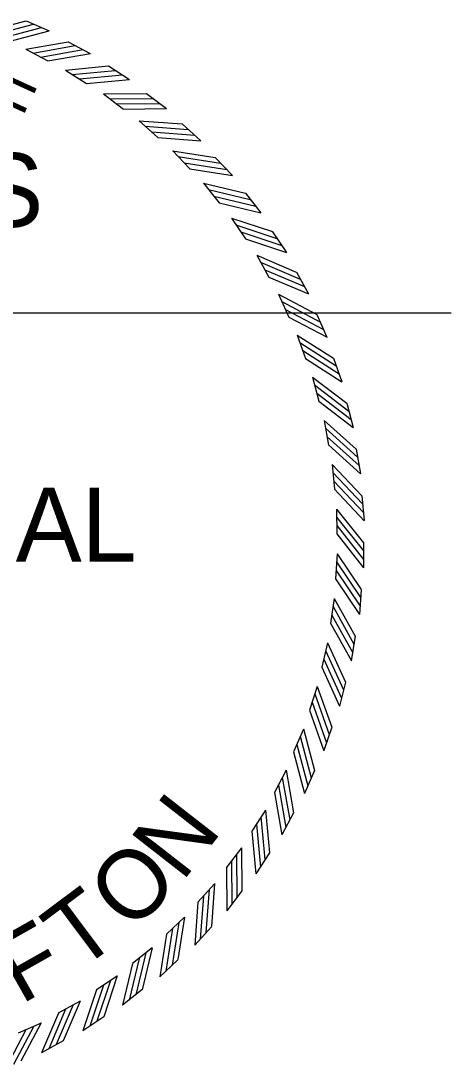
# Model space of a CAD drawing. Extents: x -712 to 3943, y 73 to 2823.
# Drawn here: x 3144.5 to 3223.6, y 210.4 to 403.1 of the extents above; entities that cross this region are included whole.
import ezdxf

# ---------------------------------------------------------------- set-up
doc = ezdxf.new("R2010")
doc.units = 0
doc.layers.add('SHET_Border-Lines', color=7, linetype='Continuous')
doc.layers.add('STAMP_TNC', color=7, linetype='Continuous')

msp = doc.modelspace()

# ---------------------------------------------------------------- linework, layer by layer
at = {"layer": 'SHET_Border-Lines'}
msp.add_lwpolyline([(2989.35, 349.36), (3223.63, 349.36)], dxfattribs=at)
msp.add_lwpolyline([(2989.35, 349.36), (3223.63, 349.36)], dxfattribs=at)
at = {"layer": 'STAMP_TNC'}
for p, q in [((3145.47, 403.1), (3149.69, 401.3)), ((3145.47, 403.1), (3149.69, 401.3)), ((3153.21, 399.26), (3157.26, 397.12)), ((3153.21, 399.26), (3157.26, 397.12)), ((3145.41, 397.88), (3149.47, 395.73)), ((3145.41, 397.88), (3149.47, 395.73)), ((3152.72, 394.07), (3156.58, 391.59)), ((3152.72, 394.07), (3156.58, 391.59)), ((3160.61, 394.81), (3164.47, 392.33)), ((3160.61, 394.81), (3164.47, 392.33)), ((3159.69, 389.67), (3163.34, 386.88)), ((3159.69, 389.67), (3163.34, 386.88)), ((3167.61, 389.75), (3171.26, 386.97)), ((3167.61, 389.75), (3171.26, 386.97)), ((3166.27, 384.71), (3169.68, 381.63)), ((3166.27, 384.71), (3169.68, 381.63)), ((3174.18, 384.14), (3177.58, 381.06)), ((3174.18, 384.14), (3177.58, 381.06)), ((3172.42, 379.22), (3175.56, 375.87)), ((3172.42, 379.22), (3175.56, 375.87)), ((3180.25, 378), (3183.39, 374.65)), ((3180.25, 378), (3183.39, 374.65)), ((3178.1, 373.25), (3180.95, 369.65)), ((3178.1, 373.25), (3180.95, 369.65)), ((3185.8, 371.38), (3188.65, 367.79)), ((3185.8, 371.38), (3188.65, 367.79)), ((3183.26, 366.82), (3185.81, 363)), ((3183.26, 366.82), (3185.81, 363)), ((3190.78, 364.32), (3193.33, 360.51)), ((3190.78, 364.32), (3193.33, 360.51)), ((3187.87, 359.99), (3190.1, 355.97)), ((3187.87, 359.99), (3190.1, 355.97)), ((3195.17, 356.88), (3197.39, 352.87)), ((3195.17, 356.88), (3197.39, 352.87)), ((3191.91, 352.8), (3193.79, 348.62)), ((3191.91, 352.8), (3193.79, 348.62)), ((3198.92, 349.1), (3200.8, 344.92)), ((3198.92, 349.1), (3200.8, 344.92)), ((3195.34, 345.31), (3196.87, 340.98)), ((3195.34, 345.31), (3196.87, 340.98)), ((3202.02, 341.04), (3203.55, 336.72)), ((3202.02, 341.04), (3203.55, 336.72)), ((3198.14, 337.56), (3199.3, 333.11)), ((3198.14, 337.56), (3199.3, 333.11)), ((3204.44, 332.75), (3205.61, 328.32)), ((3204.44, 332.75), (3205.61, 328.32)), ((3200.28, 329.6), (3201.08, 325.07)), ((3200.28, 329.6), (3201.08, 325.07)), ((3206.17, 324.29), (3206.97, 319.77)), ((3206.17, 324.29), (3206.97, 319.77)), ((3201.77, 321.49), (3202.19, 316.92)), ((3201.77, 321.49), (3202.19, 316.92)), ((3207.2, 315.71), (3207.62, 311.15)), ((3207.2, 315.71), (3207.62, 311.15)), ((3202.58, 313.29), (3202.62, 308.69)), ((3202.58, 313.29), (3202.62, 308.69)), ((3207.51, 307.08), (3207.55, 302.5)), ((3207.51, 307.08), (3207.55, 302.5)), ((3202.7, 305.05), (3202.37, 300.47)), ((3202.7, 305.05), (3202.37, 300.47)), ((3202.15, 296.82), (3201.44, 292.28)), ((3202.15, 296.82), (3201.44, 292.28)), ((3207.11, 298.45), (3206.77, 293.88)), ((3207.11, 298.45), (3206.77, 293.88)), ((3206, 289.89), (3205.28, 285.36)), ((3206, 289.89), (3205.28, 285.36)), ((3200.92, 288.67), (3199.84, 284.21)), ((3200.92, 288.67), (3199.84, 284.21)), ((3204.18, 281.44), (3203.1, 276.99)), ((3204.18, 281.44), (3203.1, 276.99)), ((3199.02, 280.65), (3197.57, 276.29)), ((3199.02, 280.65), (3197.57, 276.29)), ((3196.47, 272.81), (3194.66, 268.59)), ((3196.47, 272.81), (3194.66, 268.59)), ((3201.67, 273.18), (3200.23, 268.83)), ((3201.67, 273.18), (3200.23, 268.83)), ((3193.28, 265.21), (3191.13, 261.15)), ((3193.28, 265.21), (3191.13, 261.15)), ((3198.49, 265.15), (3196.69, 260.93)), ((3198.49, 265.15), (3196.69, 260.93)), ((3189.47, 257.9), (3186.99, 254.04)), ((3189.47, 257.9), (3186.99, 254.04)), ((3194.66, 257.41), (3192.52, 253.36)), ((3194.66, 257.41), (3192.52, 253.36)), ((3185.07, 250.93), (3182.28, 247.28)), ((3185.07, 250.93), (3182.28, 247.28)), ((3190.2, 250.01), (3187.73, 246.15)), ((3190.2, 250.01), (3187.73, 246.15)), ((3180.11, 244.35), (3177.03, 240.94)), ((3180.11, 244.35), (3177.03, 240.94)), ((3185.15, 243.01), (3182.37, 239.36)), ((3185.15, 243.01), (3182.37, 239.36)), ((3174.62, 238.2), (3171.27, 235.06)), ((3174.62, 238.2), (3171.27, 235.06)), ((3179.53, 236.44), (3176.46, 233.04)), ((3179.53, 236.44), (3176.46, 233.04)), ((3168.64, 232.52), (3165.04, 229.67)), ((3168.64, 232.52), (3165.04, 229.67)), ((3173.39, 230.37), (3170.05, 227.23)), ((3173.39, 230.37), (3170.05, 227.23)), ((3162.22, 227.36), (3158.4, 224.81)), ((3162.22, 227.36), (3158.4, 224.81)), ((3166.77, 224.82), (3163.18, 221.97)), ((3166.77, 224.82), (3163.18, 221.97)), ((3155.39, 222.75), (3151.37, 220.52)), ((3155.39, 222.75), (3151.37, 220.52)), ((3159.72, 219.84), (3155.91, 217.29)), ((3159.72, 219.84), (3155.91, 217.29)), ((3148.2, 218.71), (3144.01, 216.83)), ((3148.2, 218.71), (3144.01, 216.83)), ((3152.28, 215.45), (3148.27, 213.24)), ((3152.28, 215.45), (3148.27, 213.24))]:
    msp.add_line(p, q, dxfattribs=at)
for points in [[(3137.8, 401.07), (3145.47, 403.1)], [(3137.8, 401.07), (3145.47, 403.1)], [(3139.15, 400.48), (3146.82, 402.5)], [(3139.15, 400.48), (3146.82, 402.5)], [(3140.63, 399.89), (3148.29, 401.91)], [(3140.63, 399.89), (3148.29, 401.91)], [(3142.03, 399.27), (3149.69, 401.3)], [(3142.03, 399.27), (3149.69, 401.3)], [(3145.4, 397.88), (3153.21, 399.26)], [(3145.4, 397.88), (3153.21, 399.26)], [(3146.7, 397.18), (3154.5, 398.56)], [(3146.7, 397.18), (3154.5, 398.56)], [(3148.12, 396.46), (3155.93, 397.85)], [(3148.12, 396.46), (3155.93, 397.85)], [(3149.46, 395.74), (3157.27, 397.12)], [(3149.46, 395.74), (3157.27, 397.12)], [(3152.71, 394.07), (3160.6, 394.81)], [(3152.71, 394.07), (3160.6, 394.81)], [(3153.94, 393.26), (3161.84, 394)], [(3153.94, 393.26), (3161.84, 394)], [(3155.3, 392.43), (3163.2, 393.17)], [(3155.3, 392.43), (3163.2, 393.17)], [(3156.58, 391.6), (3164.48, 392.34)], [(3156.58, 391.6), (3164.48, 392.34)], [(3159.68, 389.67), (3167.61, 389.75)], [(3159.68, 389.67), (3167.61, 389.75)], [(3160.84, 388.76), (3168.77, 388.85)], [(3160.84, 388.76), (3168.77, 388.85)], [(3162.13, 387.83), (3170.06, 387.91)], [(3162.13, 387.83), (3170.06, 387.91)], [(3163.33, 386.89), (3171.26, 386.97)], [(3163.33, 386.89), (3171.26, 386.97)], [(3166.26, 384.71), (3174.17, 384.14)], [(3166.26, 384.71), (3174.17, 384.14)], [(3167.35, 383.71), (3175.25, 383.14)], [(3167.35, 383.71), (3175.25, 383.14)], [(3168.55, 382.67), (3176.46, 382.1)], [(3168.55, 382.67), (3176.46, 382.1)], [(3169.67, 381.64), (3177.58, 381.06)], [(3169.67, 381.64), (3177.58, 381.06)], [(3172.41, 379.22), (3180.25, 378)], [(3172.41, 379.22), (3180.25, 378)], [(3173.41, 378.14), (3181.24, 376.91)], [(3173.41, 378.14), (3181.24, 376.91)], [(3174.53, 377), (3182.36, 375.78)], [(3174.53, 377), (3182.36, 375.78)], [(3175.56, 375.88), (3183.39, 374.65)], [(3175.56, 375.88), (3183.39, 374.65)], [(3178.09, 373.25), (3185.79, 371.38)], [(3178.09, 373.25), (3185.79, 371.38)], [(3179, 372.08), (3186.7, 370.22)], [(3179, 372.08), (3186.7, 370.22)], [(3180.01, 370.86), (3187.72, 368.99)], [(3180.01, 370.86), (3187.72, 368.99)], [(3180.95, 369.65), (3188.65, 367.79)], [(3180.95, 369.65), (3188.65, 367.79)], [(3183.25, 366.82), (3190.78, 364.33)], [(3183.25, 366.82), (3190.78, 364.33)], [(3184.06, 365.59), (3191.58, 363.09)], [(3184.06, 365.59), (3191.58, 363.09)], [(3184.97, 364.28), (3192.5, 361.79)], [(3184.97, 364.28), (3192.5, 361.79)], [(3185.81, 363.01), (3193.33, 360.51)], [(3185.81, 363.01), (3193.33, 360.51)], [(3187.87, 359.99), (3195.16, 356.88)], [(3187.87, 359.99), (3195.16, 356.88)], [(3188.57, 358.7), (3195.86, 355.59)], [(3188.57, 358.7), (3195.86, 355.59)], [(3189.37, 357.32), (3196.66, 354.21)], [(3189.37, 357.32), (3196.66, 354.21)], [(3190.1, 355.98), (3197.39, 352.87)], [(3190.1, 355.98), (3197.39, 352.87)], [(3191.9, 352.81), (3198.92, 349.11)], [(3191.9, 352.81), (3198.92, 349.11)], [(3192.5, 351.46), (3199.51, 347.76)], [(3192.5, 351.46), (3199.51, 347.76)], [(3193.18, 350.02), (3200.19, 346.32)], [(3193.18, 350.02), (3200.19, 346.32)], [(3193.79, 348.62), (3200.81, 344.92)], [(3193.79, 348.62), (3200.81, 344.92)], [(3195.33, 345.31), (3202.01, 341.04)], [(3195.33, 345.31), (3202.01, 341.04)], [(3195.81, 343.92), (3202.49, 339.65)], [(3195.81, 343.92), (3202.49, 339.65)], [(3196.38, 342.43), (3203.06, 338.16)], [(3196.38, 342.43), (3203.06, 338.16)], [(3196.87, 340.99), (3203.55, 336.72)], [(3196.87, 340.99), (3203.55, 336.72)], [(3198.13, 337.56), (3204.44, 332.75)], [(3198.13, 337.56), (3204.44, 332.75)], [(3198.49, 336.13), (3204.8, 331.32)], [(3198.49, 336.13), (3204.8, 331.32)], [(3198.93, 334.6), (3205.24, 329.79)], [(3198.93, 334.6), (3205.24, 329.79)], [(3199.31, 333.12), (3205.61, 328.31)], [(3199.31, 333.12), (3205.61, 328.31)], [(3200.28, 329.6), (3206.17, 324.29)], [(3200.28, 329.6), (3206.17, 324.29)], [(3200.52, 328.15), (3206.41, 322.84)], [(3200.52, 328.15), (3206.41, 322.84)], [(3200.83, 326.59), (3206.72, 321.28)], [(3200.83, 326.59), (3206.72, 321.28)], [(3201.08, 325.08), (3206.97, 319.77)], [(3201.08, 325.08), (3206.97, 319.77)], [(3201.76, 321.49), (3207.19, 315.72)], [(3201.76, 321.49), (3207.19, 315.72)], [(3201.88, 320.03), (3207.31, 314.25)], [(3201.88, 320.03), (3207.31, 314.25)], [(3202.07, 318.44), (3207.49, 312.67)], [(3202.07, 318.44), (3207.49, 312.67)], [(3202.19, 316.92), (3207.62, 311.14)], [(3202.19, 316.92), (3207.62, 311.14)], [(3202.57, 313.29), (3207.5, 307.09)], [(3202.57, 313.29), (3207.5, 307.09)], [(3202.57, 311.82), (3207.5, 305.61)], [(3202.57, 311.82), (3207.5, 305.61)], [(3202.62, 310.23), (3207.55, 304.02)], [(3202.62, 310.23), (3207.55, 304.02)], [(3202.62, 308.7), (3207.55, 302.49)], [(3202.62, 308.7), (3207.55, 302.49)], [(3202.7, 305.05), (3207.1, 298.46)], [(3202.7, 305.05), (3207.1, 298.46)], [(3202.58, 303.58), (3206.98, 296.99)], [(3202.58, 303.58), (3206.98, 296.99)], [(3202.5, 301.99), (3206.9, 295.4)], [(3202.5, 301.99), (3206.9, 295.4)], [(3202.37, 300.47), (3206.77, 293.88)], [(3202.37, 300.47), (3206.77, 293.88)], [(3202.15, 296.83), (3205.99, 289.89)], [(3202.15, 296.83), (3205.99, 289.89)], [(3201.91, 295.37), (3205.75, 288.44)], [(3201.91, 295.37), (3205.75, 288.44)], [(3201.69, 293.79), (3205.54, 286.86)], [(3201.69, 293.79), (3205.54, 286.86)], [(3201.44, 292.29), (3205.29, 285.36)], [(3201.44, 292.29), (3205.29, 285.36)], [(3200.56, 287.25), (3203.82, 280.02)], [(3200.56, 287.25), (3203.82, 280.02)], [(3200.92, 288.68), (3204.18, 281.45)], [(3200.92, 288.68), (3204.18, 281.45)], [(3200.22, 285.69), (3203.47, 278.47)], [(3200.22, 285.69), (3203.47, 278.47)], [(3199.84, 284.21), (3203.1, 276.99)], [(3199.84, 284.21), (3203.1, 276.99)], [(3199.02, 280.66), (3201.67, 273.18)], [(3199.02, 280.66), (3201.67, 273.18)], [(3198.07, 277.74), (3200.72, 270.27)], [(3198.07, 277.74), (3200.72, 270.27)], [(3198.54, 279.26), (3201.19, 271.79)], [(3198.54, 279.26), (3201.19, 271.79)], [(3197.58, 276.3), (3200.23, 268.82)], [(3197.58, 276.3), (3200.23, 268.82)], [(3196.47, 272.82), (3198.49, 265.15)], [(3196.47, 272.82), (3198.49, 265.15)], [(3195.28, 269.99), (3197.31, 262.33)], [(3195.28, 269.99), (3197.31, 262.33)], [(3195.88, 271.47), (3197.9, 263.8)], [(3195.88, 271.47), (3197.9, 263.8)], [(3194.67, 268.59), (3196.69, 260.93)], [(3194.67, 268.59), (3196.69, 260.93)], [(3193.28, 265.22), (3194.66, 257.41)], [(3193.28, 265.22), (3194.66, 257.41)], [(3191.86, 262.5), (3193.24, 254.69)], [(3191.86, 262.5), (3193.24, 254.69)], [(3192.57, 263.92), (3193.96, 256.12)], [(3192.57, 263.92), (3193.96, 256.12)], [(3191.13, 261.16), (3192.52, 253.35)], [(3191.13, 261.16), (3192.52, 253.35)], [(3188.66, 256.68), (3189.39, 248.78)], [(3188.66, 256.68), (3189.39, 248.78)], [(3189.47, 257.91), (3190.2, 250.02)], [(3189.47, 257.91), (3190.2, 250.02)], [(3187.83, 255.32), (3188.57, 247.42)], [(3187.83, 255.32), (3188.57, 247.42)], [(3187, 254.04), (3187.73, 246.15)], [(3187, 254.04), (3187.73, 246.15)], [(3185.07, 250.94), (3185.15, 243.01)], [(3185.07, 250.94), (3185.15, 243.01)], [(3184.16, 249.78), (3184.24, 241.85)], [(3184.16, 249.78), (3184.24, 241.85)], [(3182.29, 247.29), (3182.37, 239.36)], [(3182.29, 247.29), (3182.37, 239.36)], [(3183.22, 248.49), (3183.3, 240.56)], [(3183.22, 248.49), (3183.3, 240.56)], [(3179.11, 243.27), (3178.53, 235.37)], [(3179.11, 243.27), (3178.53, 235.37)], [(3180.11, 244.36), (3179.53, 236.45)], [(3180.11, 244.36), (3179.53, 236.45)], [(3177.03, 240.95), (3176.46, 233.04)], [(3177.03, 240.95), (3176.46, 233.04)], [(3178.07, 242.07), (3177.49, 234.16)], [(3178.07, 242.07), (3177.49, 234.16)], [(3173.53, 237.21), (3172.31, 229.38)], [(3173.53, 237.21), (3172.31, 229.38)], [(3174.62, 238.21), (3173.39, 230.38)], [(3174.62, 238.21), (3173.39, 230.38)], [(3171.27, 235.06), (3170.05, 227.23)], [(3171.27, 235.06), (3170.05, 227.23)], [(3172.4, 236.09), (3171.17, 228.26)], [(3172.4, 236.09), (3171.17, 228.26)], [(3167.48, 231.63), (3165.61, 223.92)], [(3167.48, 231.63), (3165.61, 223.92)], [(3168.64, 232.53), (3166.78, 224.83)], [(3168.64, 232.53), (3166.78, 224.83)], [(3165.05, 229.67), (3163.18, 221.97)], [(3165.05, 229.67), (3163.18, 221.97)], [(3166.25, 230.61), (3164.39, 222.9)], [(3166.25, 230.61), (3164.39, 222.9)], [(3162.22, 227.37), (3159.72, 219.84)], [(3162.22, 227.37), (3159.72, 219.84)], [(3159.68, 225.65), (3157.18, 218.12)], [(3159.68, 225.65), (3157.18, 218.12)], [(3160.98, 226.56), (3158.49, 219.04)], [(3160.98, 226.56), (3158.49, 219.04)], [(3158.4, 224.81), (3155.9, 217.29)], [(3158.4, 224.81), (3155.9, 217.29)], [(3154.09, 222.05), (3150.98, 214.76)], [(3154.09, 222.05), (3150.98, 214.76)], [(3155.39, 222.75), (3152.28, 215.46)], [(3155.39, 222.75), (3152.28, 215.46)], [(3151.38, 220.52), (3148.26, 213.23)], [(3151.38, 220.52), (3148.26, 213.23)], [(3152.72, 221.25), (3149.61, 213.96)], [(3152.72, 221.25), (3149.61, 213.96)], [(3146.85, 218.12), (3143.15, 211.11)], [(3146.85, 218.12), (3143.15, 211.11)], [(3148.2, 218.72), (3144.5, 211.71)], [(3148.2, 218.72), (3144.5, 211.71)], [(3145.42, 217.44), (3141.71, 210.43)], [(3145.42, 217.44), (3141.71, 210.43)]]:
    msp.add_lwpolyline(points, dxfattribs=at)

# ---------------------------------------------------------------- texts
for s, height, rotation, p in [('F', 8.34, 335.3628, (3138.13, 385.72)), ('F', 8.34, 335.3628, (3138.13, 385.72)), ('N', 12.66, 52.0417, (3174.14, 244.48)), ('N', 12.66, 52.0417, (3174.14, 244.48)), ('O', 12.66, 44.0353, (3164.65, 235.19)), ('O', 12.66, 44.0353, (3164.65, 235.19)), ('T', 12.66, 36.7567, (3154.98, 227.96)), ('T', 12.66, 36.7567, (3154.98, 227.96)), ('F', 12.66, 29.4782, (3144.47, 222.02)), ('F', 12.66, 29.4782, (3144.47, 222.02))]:
    msp.add_text(s, height=height, rotation=rotation, dxfattribs=at).set_placement(p)
for s, height, p in [('ARKANSAS', 13.605, (3049.53, 365.2)), ('ARKANSAS', 13.605, (3049.53, 365.2)), ('PROFESSIONAL', 13.6047, (3024.26, 303.63)), ('PROFESSIONAL', 13.6047, (3024.26, 303.63))]:
    msp.add_text(s, height=height, dxfattribs=at).set_placement(p)

doc.saveas('drawing.dxf')
